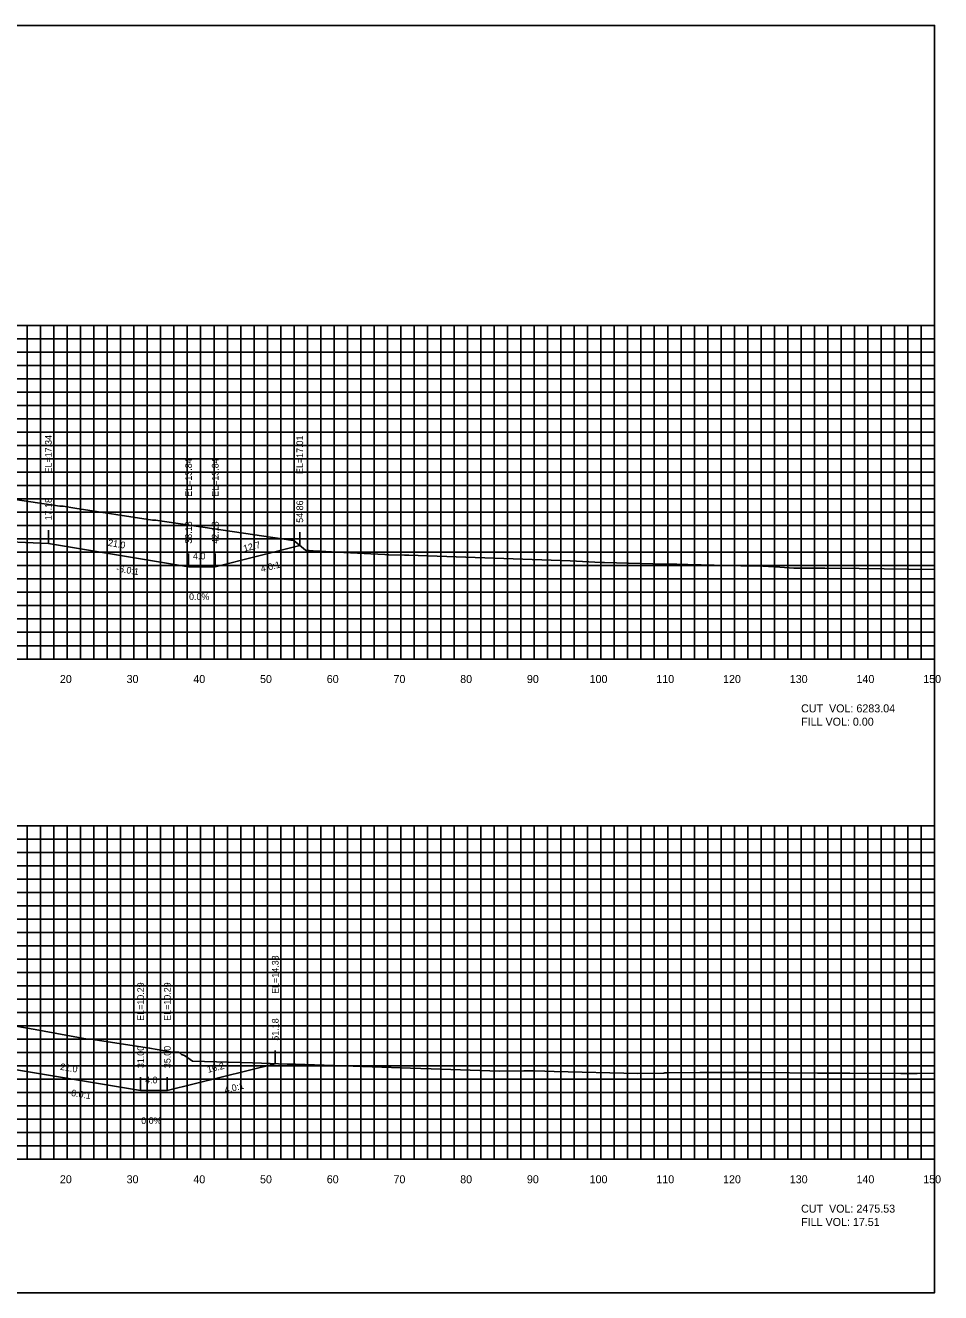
# Model space of a CAD drawing. Extents: x 1797305 to 1804485, y 245831 to 250849.
# Drawn here: x 1802644.7 to 1802781.9, y 250079.4 to 250269.4 of the extents above; entities that cross this region are included whole.
import ezdxf

# ---------------------------------------------------------------- set-up
doc = ezdxf.new("R2010")
doc.units = 0
for name, color, linetype in [('10', 7, 'Continuous'), ('29', 7, 'Continuous'), ('BASE', 7, 'Continuous'), ('CL-CNST', 7, 'Continuous'), ('EDPV-LINE', 7, 'Continuous'), ('Level 31', 7, 'Continuous'), ('LIMT-CSLINE', 7, 'Continuous'), ('M-ROADS', 7, 'Continuous')]:
    doc.layers.add(name, color=color, linetype=linetype)

msp = doc.modelspace()

# ---------------------------------------------------------------- linework, layer by layer
for p, q in [((1802648.18, 250191.77), (1802648.18, 250193.77)), ((1802685.86, 250191.44), (1802685.86, 250193.44)), ((1802669.18, 250188.27), (1802669.18, 250190.27)), ((1802673.18, 250188.27), (1802673.18, 250190.27)), ((1802682.18, 250113.76), (1802682.18, 250115.76)), ((1802662, 250109.72), (1802662, 250111.72)), ((1802666, 250109.72), (1802666, 250111.72))]:
    msp.add_line(p, q)
msp.add_lwpolyline([(1802481, 250079.43), (1802781, 250079.43), (1802781, 250269.43), (1802481, 250269.43)], close=True)
at = {"layer": '29'}
for p, q in [((1802481, 250224.43), (1802781, 250224.43)), ((1802645, 250174.43), (1802645, 250224.43)), ((1802647, 250174.43), (1802647, 250224.43)), ((1802649, 250174.43), (1802649, 250224.43)), ((1802651, 250174.43), (1802651, 250224.43)), ((1802653, 250174.43), (1802653, 250224.43)), ((1802655, 250174.43), (1802655, 250224.43)), ((1802657, 250174.43), (1802657, 250224.43)), ((1802659, 250174.43), (1802659, 250224.43)), ((1802661, 250174.43), (1802661, 250224.43)), ((1802663, 250174.43), (1802663, 250224.43)), ((1802665, 250174.43), (1802665, 250224.43)), ((1802667, 250174.43), (1802667, 250224.43)), ((1802669, 250174.43), (1802669, 250224.43)), ((1802671, 250174.43), (1802671, 250224.43)), ((1802673, 250174.43), (1802673, 250224.43)), ((1802675, 250174.43), (1802675, 250224.43)), ((1802677, 250174.43), (1802677, 250224.43)), ((1802679, 250174.43), (1802679, 250224.43)), ((1802681, 250174.43), (1802681, 250224.43)), ((1802683, 250174.43), (1802683, 250224.43)), ((1802685, 250174.43), (1802685, 250224.43)), ((1802687, 250174.43), (1802687, 250224.43)), ((1802689, 250174.43), (1802689, 250224.43)), ((1802691, 250174.43), (1802691, 250224.43)), ((1802693, 250174.43), (1802693, 250224.43)), ((1802695, 250174.43), (1802695, 250224.43)), ((1802697, 250174.43), (1802697, 250224.43)), ((1802699, 250174.43), (1802699, 250224.43)), ((1802701, 250174.43), (1802701, 250224.43)), ((1802703, 250174.43), (1802703, 250224.43)), ((1802705, 250174.43), (1802705, 250224.43)), ((1802707, 250174.43), (1802707, 250224.43)), ((1802709, 250174.43), (1802709, 250224.43)), ((1802711, 250174.43), (1802711, 250224.43)), ((1802713, 250174.43), (1802713, 250224.43)), ((1802715, 250174.43), (1802715, 250224.43)), ((1802717, 250174.43), (1802717, 250224.43)), ((1802719, 250174.43), (1802719, 250224.43)), ((1802721, 250174.43), (1802721, 250224.43)), ((1802723, 250174.43), (1802723, 250224.43)), ((1802725, 250174.43), (1802725, 250224.43)), ((1802727, 250174.43), (1802727, 250224.43)), ((1802729, 250174.43), (1802729, 250224.43)), ((1802731, 250174.43), (1802731, 250224.43)), ((1802733, 250174.43), (1802733, 250224.43)), ((1802735, 250174.43), (1802735, 250224.43)), ((1802737, 250174.43), (1802737, 250224.43)), ((1802739, 250174.43), (1802739, 250224.43)), ((1802741, 250174.43), (1802741, 250224.43)), ((1802743, 250174.43), (1802743, 250224.43)), ((1802745, 250174.43), (1802745, 250224.43)), ((1802747, 250174.43), (1802747, 250224.43)), ((1802749, 250174.43), (1802749, 250224.43)), ((1802751, 250174.43), (1802751, 250224.43)), ((1802753, 250174.43), (1802753, 250224.43)), ((1802755, 250174.43), (1802755, 250224.43)), ((1802757, 250174.43), (1802757, 250224.43)), ((1802759, 250174.43), (1802759, 250224.43)), ((1802761, 250174.43), (1802761, 250224.43)), ((1802763, 250174.43), (1802763, 250224.43)), ((1802765, 250174.43), (1802765, 250224.43)), ((1802767, 250174.43), (1802767, 250224.43)), ((1802769, 250174.43), (1802769, 250224.43)), ((1802771, 250174.43), (1802771, 250224.43)), ((1802773, 250174.43), (1802773, 250224.43)), ((1802775, 250174.43), (1802775, 250224.43)), ((1802777, 250174.43), (1802777, 250224.43)), ((1802779, 250174.43), (1802779, 250224.43)), ((1802781, 250174.43), (1802781, 250224.43)), ((1802481, 250222.43), (1802781, 250222.43)), ((1802481, 250220.43), (1802781, 250220.43)), ((1802481, 250218.43), (1802781, 250218.43)), ((1802481, 250216.43), (1802781, 250216.43)), ((1802481, 250214.43), (1802781, 250214.43)), ((1802481, 250212.43), (1802781, 250212.43)), ((1802481, 250210.43), (1802781, 250210.43)), ((1802481, 250208.43), (1802781, 250208.43)), ((1802481, 250206.43), (1802781, 250206.43)), ((1802481, 250204.43), (1802781, 250204.43)), ((1802481, 250202.43), (1802781, 250202.43)), ((1802481, 250200.43), (1802781, 250200.43)), ((1802481, 250198.43), (1802781, 250198.43)), ((1802481, 250196.43), (1802781, 250196.43)), ((1802481, 250194.43), (1802781, 250194.43)), ((1802481, 250192.43), (1802781, 250192.43)), ((1802481, 250190.43), (1802781, 250190.43)), ((1802481, 250188.43), (1802781, 250188.43)), ((1802481, 250186.43), (1802781, 250186.43)), ((1802481, 250184.43), (1802781, 250184.43)), ((1802481, 250182.43), (1802781, 250182.43)), ((1802481, 250180.43), (1802781, 250180.43)), ((1802481, 250178.43), (1802781, 250178.43)), ((1802481, 250176.43), (1802781, 250176.43)), ((1802481, 250174.43), (1802781, 250174.43)), ((1802481, 250149.43), (1802781, 250149.43)), ((1802645, 250099.43), (1802645, 250149.43)), ((1802647, 250099.43), (1802647, 250149.43)), ((1802649, 250099.43), (1802649, 250149.43)), ((1802651, 250099.43), (1802651, 250149.43)), ((1802653, 250099.43), (1802653, 250149.43)), ((1802655, 250099.43), (1802655, 250149.43)), ((1802657, 250099.43), (1802657, 250149.43)), ((1802659, 250099.43), (1802659, 250149.43)), ((1802661, 250099.43), (1802661, 250149.43)), ((1802663, 250099.43), (1802663, 250149.43)), ((1802665, 250099.43), (1802665, 250149.43)), ((1802667, 250099.43), (1802667, 250149.43)), ((1802669, 250099.43), (1802669, 250149.43)), ((1802671, 250099.43), (1802671, 250149.43)), ((1802673, 250099.43), (1802673, 250149.43)), ((1802675, 250099.43), (1802675, 250149.43)), ((1802677, 250099.43), (1802677, 250149.43)), ((1802679, 250099.43), (1802679, 250149.43)), ((1802681, 250099.43), (1802681, 250149.43)), ((1802683, 250099.43), (1802683, 250149.43)), ((1802685, 250099.43), (1802685, 250149.43)), ((1802687, 250099.43), (1802687, 250149.43)), ((1802689, 250099.43), (1802689, 250149.43)), ((1802691, 250099.43), (1802691, 250149.43)), ((1802693, 250099.43), (1802693, 250149.43)), ((1802695, 250099.43), (1802695, 250149.43)), ((1802697, 250099.43), (1802697, 250149.43)), ((1802699, 250099.43), (1802699, 250149.43)), ((1802701, 250099.43), (1802701, 250149.43)), ((1802703, 250099.43), (1802703, 250149.43)), ((1802705, 250099.43), (1802705, 250149.43)), ((1802707, 250099.43), (1802707, 250149.43)), ((1802709, 250099.43), (1802709, 250149.43)), ((1802711, 250099.43), (1802711, 250149.43)), ((1802713, 250099.43), (1802713, 250149.43)), ((1802715, 250099.43), (1802715, 250149.43)), ((1802717, 250099.43), (1802717, 250149.43)), ((1802719, 250099.43), (1802719, 250149.43)), ((1802721, 250099.43), (1802721, 250149.43)), ((1802723, 250099.43), (1802723, 250149.43)), ((1802725, 250099.43), (1802725, 250149.43)), ((1802727, 250099.43), (1802727, 250149.43)), ((1802729, 250099.43), (1802729, 250149.43)), ((1802731, 250099.43), (1802731, 250149.43)), ((1802733, 250099.43), (1802733, 250149.43)), ((1802735, 250099.43), (1802735, 250149.43)), ((1802737, 250099.43), (1802737, 250149.43)), ((1802739, 250099.43), (1802739, 250149.43)), ((1802741, 250099.43), (1802741, 250149.43)), ((1802743, 250099.43), (1802743, 250149.43)), ((1802745, 250099.43), (1802745, 250149.43)), ((1802747, 250099.43), (1802747, 250149.43)), ((1802749, 250099.43), (1802749, 250149.43)), ((1802751, 250099.43), (1802751, 250149.43)), ((1802753, 250099.43), (1802753, 250149.43)), ((1802755, 250099.43), (1802755, 250149.43)), ((1802757, 250099.43), (1802757, 250149.43)), ((1802759, 250099.43), (1802759, 250149.43)), ((1802761, 250099.43), (1802761, 250149.43)), ((1802763, 250099.43), (1802763, 250149.43)), ((1802765, 250099.43), (1802765, 250149.43)), ((1802767, 250099.43), (1802767, 250149.43)), ((1802769, 250099.43), (1802769, 250149.43)), ((1802771, 250099.43), (1802771, 250149.43)), ((1802773, 250099.43), (1802773, 250149.43)), ((1802775, 250099.43), (1802775, 250149.43)), ((1802777, 250099.43), (1802777, 250149.43)), ((1802779, 250099.43), (1802779, 250149.43)), ((1802781, 250099.43), (1802781, 250149.43)), ((1802481, 250147.43), (1802781, 250147.43)), ((1802481, 250145.43), (1802781, 250145.43)), ((1802481, 250143.43), (1802781, 250143.43)), ((1802481, 250141.43), (1802781, 250141.43)), ((1802481, 250139.43), (1802781, 250139.43)), ((1802481, 250137.43), (1802781, 250137.43)), ((1802481, 250135.43), (1802781, 250135.43)), ((1802481, 250133.43), (1802781, 250133.43)), ((1802481, 250131.43), (1802781, 250131.43)), ((1802481, 250129.43), (1802781, 250129.43)), ((1802481, 250127.43), (1802781, 250127.43)), ((1802481, 250125.43), (1802781, 250125.43)), ((1802481, 250123.43), (1802781, 250123.43)), ((1802481, 250121.43), (1802781, 250121.43)), ((1802481, 250119.43), (1802781, 250119.43)), ((1802481, 250117.43), (1802781, 250117.43)), ((1802481, 250115.43), (1802781, 250115.43)), ((1802481, 250113.43), (1802781, 250113.43)), ((1802481, 250111.43), (1802781, 250111.43)), ((1802481, 250109.43), (1802781, 250109.43)), ((1802481, 250107.43), (1802781, 250107.43)), ((1802481, 250105.43), (1802781, 250105.43)), ((1802481, 250103.43), (1802781, 250103.43)), ((1802481, 250101.43), (1802781, 250101.43)), ((1802481, 250099.43), (1802781, 250099.43))]:
    msp.add_line(p, q, dxfattribs=at)
at = {"layer": 'CL-CNST'}
for points in [[(1802481, 250197.86), (1802568.83, 250189.08), (1802572.83, 250189.08), (1802593.83, 250192.58), (1802603, 250192.95), (1802607, 250192.99), (1802631, 250192.46), (1802639, 250192.14), (1802648.18, 250191.77), (1802669.18, 250188.27), (1802673.18, 250188.27), (1802685.86, 250191.44)], [(1802534.26, 250114.59), (1802576, 250110.42), (1802580, 250110.42), (1802601, 250113.92), (1802603, 250114), (1802607, 250114.15), (1802631, 250113.62), (1802639, 250113.3), (1802641, 250113.22), (1802662, 250109.72), (1802666, 250109.72), (1802682.18, 250113.76)]]:
    msp.add_lwpolyline(points, dxfattribs=at)
at = {"layer": 'Level 31'}
for p, q in [((1802781, 250174.43), (1802781, 250224.43)), ((1802781.06, 250224.43), (1802781, 250224.43)), ((1802781.06, 250214.43), (1802781, 250214.43)), ((1802781.06, 250204.43), (1802781, 250204.43)), ((1802781.06, 250194.43), (1802781, 250194.43)), ((1802781.06, 250184.43), (1802781, 250184.43)), ((1802481, 250174.43), (1802781, 250174.43)), ((1802651, 250174.37), (1802651, 250174.43)), ((1802661, 250174.37), (1802661, 250174.43)), ((1802671, 250174.37), (1802671, 250174.43)), ((1802681, 250174.37), (1802681, 250174.43)), ((1802691, 250174.37), (1802691, 250174.43)), ((1802701, 250174.37), (1802701, 250174.43)), ((1802711, 250174.37), (1802711, 250174.43)), ((1802721, 250174.37), (1802721, 250174.43)), ((1802731, 250174.37), (1802731, 250174.43)), ((1802741, 250174.37), (1802741, 250174.43)), ((1802751, 250174.37), (1802751, 250174.43)), ((1802761, 250174.37), (1802761, 250174.43)), ((1802771, 250174.37), (1802771, 250174.43)), ((1802781, 250174.37), (1802781, 250174.43)), ((1802781.06, 250174.43), (1802781, 250174.43)), ((1802781, 250099.43), (1802781, 250149.43)), ((1802781.06, 250149.43), (1802781, 250149.43)), ((1802781.06, 250139.43), (1802781, 250139.43)), ((1802781.06, 250129.43), (1802781, 250129.43)), ((1802781.06, 250119.43), (1802781, 250119.43)), ((1802781.06, 250109.43), (1802781, 250109.43)), ((1802481, 250099.43), (1802781, 250099.43)), ((1802651, 250099.37), (1802651, 250099.43)), ((1802661, 250099.37), (1802661, 250099.43)), ((1802671, 250099.37), (1802671, 250099.43)), ((1802681, 250099.37), (1802681, 250099.43)), ((1802691, 250099.37), (1802691, 250099.43)), ((1802701, 250099.37), (1802701, 250099.43)), ((1802711, 250099.37), (1802711, 250099.43)), ((1802721, 250099.37), (1802721, 250099.43)), ((1802731, 250099.37), (1802731, 250099.43)), ((1802741, 250099.37), (1802741, 250099.43)), ((1802751, 250099.37), (1802751, 250099.43)), ((1802761, 250099.37), (1802761, 250099.43)), ((1802771, 250099.37), (1802771, 250099.43)), ((1802781, 250099.37), (1802781, 250099.43)), ((1802781.06, 250099.43), (1802781, 250099.43))]:
    msp.add_line(p, q, dxfattribs=at)
at = {"layer": 'M-ROADS'}
for points in [[(1802640.82, 250198.71), (1802649.88, 250197.34), (1802649.95, 250197.34), (1802650.38, 250197.34), (1802652.13, 250197.07), (1802663.79, 250195.26), (1802663.81, 250195.26), (1802664.29, 250195.26), (1802664.87, 250195.17), (1802668.68, 250194.6), (1802669.99, 250194.41), (1802684.86, 250192.18), (1802684.98, 250192.18), (1802686.69, 250190.75), (1802686.77, 250190.68), (1802686.8, 250190.68), (1802687.27, 250190.68), (1802688.52, 250190.62), (1802688.92, 250190.6), (1802691.44, 250190.46), (1802696.51, 250190.22), (1802698.59, 250190.08), (1802698.65, 250190.08), (1802699.1, 250190.07), (1802699.2, 250190.07), (1802701.56, 250190.02), (1802702.21, 250190.01), (1802726.38, 250189.13), (1802731.05, 250188.91), (1802731.18, 250188.91), (1802731.55, 250188.91), (1802740.57, 250188.65), (1802741.89, 250188.64), (1802742.34, 250188.64), (1802742.39, 250188.64), (1802744.01, 250188.59), (1802751.97, 250188.39), (1802752.24, 250188.39), (1802755.26, 250188.34), (1802757.79, 250188.2), (1802759.91, 250188.03), (1802762.09, 250188.03), (1802762.83, 250188.03), (1802763.75, 250188.04), (1802763.91, 250188.04), (1802763.99, 250188.04), (1802764.1, 250188.05), (1802764.23, 250188.05), (1802764.4, 250188.05), (1802764.55, 250188.06), (1802769.68, 250187.99), (1802780.88, 250187.84), (1802781, 250187.84)], [(1802635.7, 250120.7), (1802646.17, 250118.87), (1802654.06, 250117.44), (1802654.24, 250117.44), (1802654.56, 250117.44), (1802663.35, 250116.09), (1802666.77, 250115.5), (1802666.85, 250115.5), (1802667.22, 250115.48), (1802667.57, 250115.48), (1802667.71, 250115.48), (1802668.16, 250115.11), (1802668.29, 250115.11), (1802668.56, 250114.99), (1802669.78, 250114.16), (1802678.78, 250113.9), (1802680.13, 250113.84), (1802683.99, 250113.69), (1802684.46, 250113.69), (1802685.19, 250113.69), (1802685.22, 250113.69), (1802702.46, 250113.1), (1802705.53, 250112.99), (1802715.78, 250112.64), (1802719.44, 250112.67), (1802719.46, 250112.67), (1802719.94, 250112.67), (1802720.89, 250112.67), (1802722.58, 250112.62), (1802723.97, 250112.58), (1802736.52, 250112.31), (1802740.42, 250112.36), (1802740.56, 250112.37), (1802740.86, 250112.37), (1802745.8, 250112.44), (1802754.61, 250112.42), (1802754.79, 250112.42), (1802755.11, 250112.42), (1802763.46, 250112.32), (1802767.83, 250112.33), (1802768.01, 250112.33), (1802768.32, 250112.33), (1802775.96, 250112.29), (1802776.1, 250112.29), (1802776.12, 250112.29), (1802776.12, 250112.29), (1802776.5, 250112.29), (1802778.4, 250112.31), (1802781, 250112.34)]]:
    msp.add_lwpolyline(points, dxfattribs=at)

# ---------------------------------------------------------------- texts
for s, rotation, p in [('-6.0:1', 350.5377, (1802658.27, 250187.56)), ('4.0:1', 14.0362, (1802680.13, 250187.43)), ('4.0:1', 14.0362, (1802674.7, 250109.31)), ('-6.0:1', 350.5377, (1802651.09, 250109))]:
    msp.add_text(s, height=1, rotation=rotation).set_placement(p)
at = {"layer": '10'}
for s, p in [('20', (1802649.9, 250170.83)), ('30', (1802659.9, 250170.83)), ('40', (1802669.9, 250170.83)), ('50', (1802679.9, 250170.83)), ('60', (1802689.9, 250170.83)), ('70', (1802699.9, 250170.83)), ('80', (1802709.9, 250170.83)), ('90', (1802719.9, 250170.83)), ('100', (1802729.3, 250170.83)), ('110', (1802739.3, 250170.83)), ('120', (1802749.3, 250170.83)), ('130', (1802759.3, 250170.83)), ('140', (1802769.3, 250170.83)), ('150', (1802779.3, 250170.83)), ('20', (1802649.9, 250095.83)), ('30', (1802659.9, 250095.83)), ('40', (1802669.9, 250095.83)), ('50', (1802679.9, 250095.83)), ('60', (1802689.9, 250095.83)), ('70', (1802699.9, 250095.83)), ('80', (1802709.9, 250095.83)), ('90', (1802719.9, 250095.83)), ('100', (1802729.3, 250095.83)), ('110', (1802739.3, 250095.83)), ('120', (1802749.3, 250095.83)), ('130', (1802759.3, 250095.83)), ('140', (1802769.3, 250095.83)), ('150', (1802779.3, 250095.83))]:
    msp.add_text(s, height=1.2, dxfattribs=at).set_placement(p)
at = {"layer": 'BASE'}
for s, rotation, p in [('21.0', 350.5377, (1802657.06, 250191.41)), ('12.7', 14.0362, (1802677.53, 250190.49)), ('21.0', 350.5377, (1802649.89, 250112.85)), ('16.2', 14.0362, (1802672.1, 250112.38))]:
    msp.add_text(s, height=1, rotation=rotation, dxfattribs=at).set_placement(p)
for s, p in [('4.0', (1802669.85, 250189.37)), ('0.0%', (1802669.26, 250183.27)), ('4.0', (1802662.68, 250110.82)), ('0.0%', (1802662.09, 250104.72))]:
    msp.add_text(s, height=1, dxfattribs=at).set_placement(p)
at = {"layer": 'EDPV-LINE'}
for s, p in [('CUT  VOL: 6283.04', (1802761, 250166.43)), ('FILL VOL: 0.00', (1802761, 250164.43)), ('CUT  VOL: 2475.53', (1802761, 250091.43)), ('FILL VOL: 17.51', (1802761, 250089.43))]:
    msp.add_text(s, height=1.2, dxfattribs=at).set_placement(p)
at = {"layer": 'LIMT-CSLINE'}
for s, p in [('EL=17.34', (1802648.68, 250202.25)), ('EL=17.01', (1802686.36, 250202.17)), ('EL=13.84', (1802669.68, 250198.75)), ('EL=13.84', (1802673.68, 250198.75)), ('17.18', (1802648.68, 250195.22)), ('54.86', (1802686.36, 250194.85)), ('38.18', (1802669.68, 250191.72)), ('42.18', (1802673.68, 250191.72)), ('EL=14.33', (1802682.68, 250124.23)), ('EL=10.29', (1802662.5, 250120.19)), ('EL=10.29', (1802666.5, 250120.19)), ('51.18', (1802682.68, 250117.21)), ('31.00', (1802662.5, 250113.09)), ('35.00', (1802666.5, 250113.09))]:
    msp.add_text(s, height=1, rotation=90, dxfattribs=at).set_placement(p)

doc.saveas('drawing.dxf')
